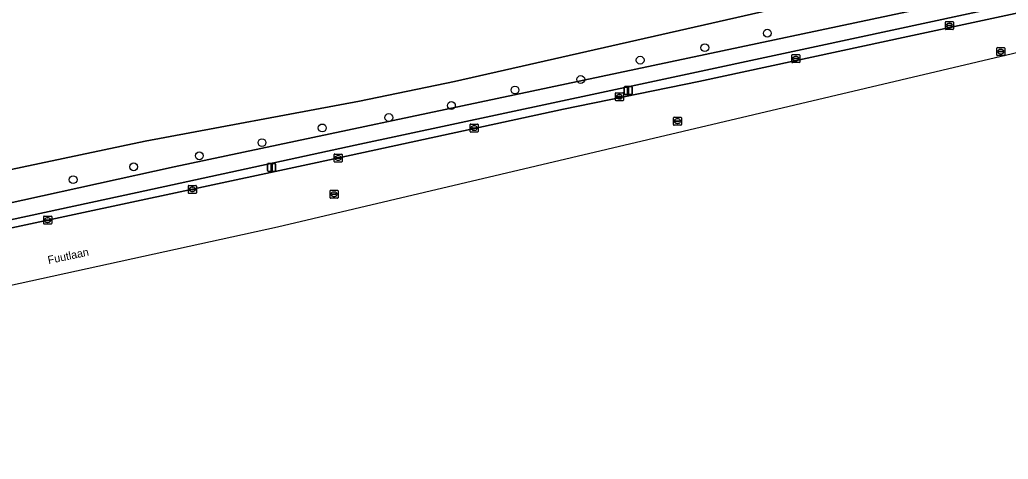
# Model space of a CAD drawing. Extents: x 161477 to 163040, y 383680 to 384871.
# Drawn here: x 162018.6 to 162142.1, y 383712.9 to 383767.8 of the extents above; entities that cross this region are included whole.
import ezdxf

# ---------------------------------------------------------------- set-up
doc = ezdxf.new("R2010")
doc.units = 0
for name, color, linetype in [('IMGEO_Boom', 7, 'Continuous'), ('IMGEO_Erf', 7, 'Continuous'), ('IMGEO_Groenvoorziening', 7, 'Continuous'), ('IMGEO_Hek', 7, 'Continuous'), ('IMGEO_Kolk', 7, 'Continuous'), ('IMGEO_Lichtmast', 7, 'Continuous'), ('IMGEO_Openbare_ruimte_label', 7, 'Continuous'), ('IMGEO_Rijbaan_lokaal_open', 7, 'Continuous'), ('IMGEO_Rioolput', 7, 'Continuous'), ('IMGEO_Voetpad_open', 7, 'Continuous')]:
    doc.layers.add(name, color=color, linetype=linetype)

msp = doc.modelspace()

# ---------------------------------------------------------------- linework, layer by layer
at = {"layer": 'IMGEO_Boom'}
for centre in [(162111.98, 383766.1), (162104.17, 383764.29), (162096.09, 383762.73), (162088.67, 383760.32), (162080.44, 383759), (162072.5, 383757.06), (162064.68, 383755.56), (162056.36, 383754.26), (162048.83, 383752.42), (162041, 383750.78), (162032.8, 383749.4), (162025.23, 383747.79)]:
    msp.add_circle(centre, 0.489, dxfattribs=at)
at = {"layer": 'IMGEO_Erf'}
msp.add_lwpolyline([(161913.96, 383727.2), (162034.23, 383752.62), (162061.02, 383757.62), (162072.88, 383760.06), (162200.21, 383788.99), (162215.71, 383792.24), (162226.94, 383794.59), (162253.58, 383800.74), (162261.09, 383802.89), (162298.92, 383814.56), (162300.16, 383814.95), (162305.42, 383816.57), (162306.83, 383817), (162311.78, 383818.53), (162312.56, 383818.77), (162312.8, 383817.2), (162313.95, 383815.04), (162315.67, 383812.77), (162316.14, 383812.14)], dxfattribs=at)
at = {"layer": 'IMGEO_Groenvoorziening'}
for points in [[(162298.92, 383814.56), (162261.09, 383802.89), (162253.58, 383800.74), (162226.94, 383794.59), (162215.71, 383792.24), (162200.21, 383788.99), (162072.88, 383760.06), (162061.02, 383757.62), (162034.23, 383752.62), (161913.96, 383727.2)], [(162007.91, 383740.73), (162033.22, 383746.19), (162060.49, 383752.12), (162097.3, 383759.98), (162118.07, 383764.45), (162141.54, 383769.48), (162180.49, 383777.87), (162190.22, 383779.97), (162198.07, 383781.8), (162206.11, 383783.95), (162214.63, 383786.44), (162216.75, 383787.01), (162217.08, 383787.12), (162231.35, 383791.72), (162216.7, 383788.57), (162197.76, 383783.49), (162191.42, 383781.95), (162037.84, 383749.41), (161933.79, 383726.48)], [(161933.79, 383726.48), (162037.84, 383749.41), (162191.42, 383781.95), (162197.76, 383783.49), (162216.7, 383788.57)]]:
    msp.add_lwpolyline(points, dxfattribs=at)
at = {"layer": 'IMGEO_Hek'}
for points in [[(162061.02, 383757.62), (162072.88, 383760.06), (162200.21, 383788.99), (162215.71, 383792.24)], [(161846.44, 383712.85), (161847.77, 383713.09), (161851.78, 383713.8), (161862.58, 383715.7), (161882.57, 383720.16), (161913.96, 383727.2), (162034.23, 383752.62), (162061.02, 383757.62)]]:
    msp.add_lwpolyline(points, dxfattribs=at)
at = {"layer": 'IMGEO_Kolk'}
for p, q in [((162134.23, 383766.63), (162134.23, 383767.49)), ((162134.3, 383767.56), (162135.15, 383767.56)), ((162134.72, 383767.34), (162134.74, 383767.34)), ((162135.23, 383767.49), (162135.23, 383766.63)), ((162135.15, 383766.56), (162134.3, 383766.56)), ((162134.49, 383767.05), (162134.49, 383767.07)), ((162134.53, 383767.1), (162134.93, 383767.1)), ((162134.92, 383767.02), (162134.53, 383767.02)), ((162134.74, 383766.78), (162134.71, 383766.78)), ((162134.97, 383767.07), (162134.97, 383767.05)), ((162115.04, 383762.49), (162115.04, 383763.35)), ((162115.11, 383763.42), (162115.96, 383763.42)), ((162115.96, 383762.42), (162115.11, 383762.42)), ((162115.3, 383762.91), (162115.3, 383762.93)), ((162115.34, 383762.96), (162115.74, 383762.96)), ((162115.73, 383762.88), (162115.34, 383762.88)), ((162115.55, 383762.64), (162115.52, 383762.64)), ((162115.53, 383763.2), (162115.55, 383763.2)), ((162115.78, 383762.93), (162115.78, 383762.91)), ((162116.04, 383763.35), (162116.04, 383762.49)), ((162093.07, 383758.66), (162093.92, 383758.66)), ((162092.99, 383757.74), (162092.99, 383758.59)), ((162093.92, 383757.66), (162093.07, 383757.66)), ((162093.25, 383758.16), (162093.25, 383758.17)), ((162093.29, 383758.21), (162093.69, 383758.21)), ((162093.69, 383758.12), (162093.29, 383758.12)), ((162093.48, 383758.44), (162093.51, 383758.44)), ((162093.5, 383757.88), (162093.48, 383757.88)), ((162093.74, 383758.17), (162093.74, 383758.16)), ((162093.99, 383758.59), (162093.99, 383757.74)), ((162074.84, 383753.81), (162074.84, 383754.67)), ((162074.91, 383754.74), (162075.76, 383754.74)), ((162075.76, 383753.74), (162074.91, 383753.74)), ((162075.09, 383754.23), (162075.09, 383754.25)), ((162075.53, 383754.2), (162075.13, 383754.2)), ((162075.14, 383754.28), (162075.54, 383754.28)), ((162075.32, 383754.52), (162075.35, 383754.52)), ((162075.35, 383753.96), (162075.32, 383753.96)), ((162075.58, 383754.25), (162075.58, 383754.23)), ((162075.84, 383754.67), (162075.84, 383753.81)), ((162057.85, 383750.08), (162057.85, 383750.93)), ((162057.92, 383751), (162058.77, 383751)), ((162058.77, 383750), (162057.92, 383750)), ((162058.11, 383750.5), (162058.11, 383750.51)), ((162058.15, 383750.55), (162058.55, 383750.55)), ((162058.54, 383750.46), (162058.15, 383750.46)), ((162058.36, 383750.22), (162058.33, 383750.22)), ((162058.34, 383750.78), (162058.36, 383750.78)), ((162058.59, 383750.51), (162058.59, 383750.5)), ((162058.85, 383750.93), (162058.85, 383750.08)), ((162039.63, 383746.15), (162039.63, 383747)), ((162039.7, 383747.08), (162040.56, 383747.08)), ((162039.89, 383746.57), (162039.89, 383746.58)), ((162039.93, 383746.62), (162040.33, 383746.62)), ((162040.32, 383746.53), (162039.93, 383746.53)), ((162040.14, 383746.3), (162040.11, 383746.3)), ((162040.12, 383746.86), (162040.14, 383746.86)), ((162040.37, 383746.58), (162040.37, 383746.57)), ((162040.63, 383747), (162040.63, 383746.15)), ((162040.56, 383746.08), (162039.7, 383746.08)), ((162021.55, 383742.31), (162021.55, 383743.17)), ((162021.62, 383743.24), (162022.47, 383743.24)), ((162021.81, 383742.73), (162021.81, 383742.75)), ((162021.85, 383742.78), (162022.25, 383742.78)), ((162022.24, 383742.7), (162021.85, 383742.7)), ((162022.04, 383743.02), (162022.06, 383743.02)), ((162022.29, 383742.75), (162022.29, 383742.73)), ((162022.55, 383743.17), (162022.55, 383742.31)), ((162022.47, 383742.24), (162021.62, 383742.24)), ((162022.06, 383742.46), (162022.03, 383742.46))]:
    msp.add_line(p, q, dxfattribs=at)
for points in [[(162134.23, 383766.63), (162134.23, 383767.49)], [(162134.3, 383767.56), (162135.15, 383767.56)], [(162135.23, 383767.49), (162135.23, 383766.63)], [(162135.15, 383766.56), (162134.3, 383766.56)], [(162115.04, 383762.49), (162115.04, 383763.35)], [(162115.11, 383763.42), (162115.96, 383763.42)], [(162115.96, 383762.42), (162115.11, 383762.42)], [(162116.04, 383763.35), (162116.04, 383762.49)], [(162093.07, 383758.66), (162093.92, 383758.66)], [(162092.99, 383757.74), (162092.99, 383758.59)], [(162093.92, 383757.66), (162093.07, 383757.66)], [(162093.99, 383758.59), (162093.99, 383757.74)], [(162074.84, 383753.81), (162074.84, 383754.67)], [(162074.91, 383754.74), (162075.76, 383754.74)], [(162075.76, 383753.74), (162074.91, 383753.74)], [(162075.84, 383754.67), (162075.84, 383753.81)], [(162057.85, 383750.08), (162057.85, 383750.93)], [(162057.92, 383751), (162058.77, 383751)], [(162058.77, 383750), (162057.92, 383750)], [(162058.85, 383750.93), (162058.85, 383750.08)], [(162039.63, 383746.15), (162039.63, 383747)], [(162039.7, 383747.08), (162040.56, 383747.08)], [(162040.63, 383747), (162040.63, 383746.15)], [(162040.56, 383746.08), (162039.7, 383746.08)], [(162021.55, 383742.31), (162021.55, 383743.17)], [(162021.62, 383743.24), (162022.47, 383743.24)], [(162022.55, 383743.17), (162022.55, 383742.31)], [(162022.47, 383742.24), (162021.62, 383742.24)]]:
    msp.add_lwpolyline(points, dxfattribs=at)
for centre, radius, start, end in [((162134.3, 383767.48), 0.0765, 91.552, 178.448), ((162134.3, 383767.48), 0.0765, 91.552, 178.448), ((162135.15, 383767.48), 0.0765, 1.552, 88.448), ((162135.15, 383767.48), 0.0765, 1.552, 88.448), ((162134.3, 383766.63), 0.0765, 181.552, 268.448), ((162134.3, 383766.63), 0.0765, 181.552, 268.448), ((162134.53, 383767.06), 0.0403, 85.8775, 175.7526), ((162134.52, 383767.05), 0.0366, 178.938, 274.7102), ((162134.93, 383767.06), 0.043, 264.8664, 352.4533), ((162134.93, 383767.06), 0.0386, 1.7309, 96.639), ((162135.15, 383766.63), 0.0765, 271.552, 358.448), ((162135.15, 383766.63), 0.0765, 271.552, 358.448), ((162115.11, 383763.34), 0.0765, 91.552, 178.448), ((162115.11, 383763.34), 0.0765, 91.552, 178.448), ((162115.11, 383762.49), 0.0765, 181.552, 268.448), ((162115.11, 383762.49), 0.0765, 181.552, 268.448), ((162115.34, 383762.92), 0.0403, 85.8775, 175.7526), ((162115.33, 383762.91), 0.0366, 178.938, 274.7102), ((162115.74, 383762.92), 0.043, 264.8664, 352.4533), ((162115.74, 383762.92), 0.0386, 1.7309, 96.639), ((162115.96, 383763.34), 0.0765, 1.552, 88.448), ((162115.96, 383763.34), 0.0765, 1.552, 88.448), ((162115.96, 383762.49), 0.0765, 271.552, 358.448), ((162115.96, 383762.49), 0.0765, 271.552, 358.448), ((162093.07, 383758.59), 0.0765, 91.552, 178.448), ((162093.07, 383758.59), 0.0765, 91.552, 178.448), ((162093.92, 383758.59), 0.0765, 1.552, 88.448), ((162093.92, 383758.59), 0.0765, 1.552, 88.448), ((162093.07, 383757.74), 0.0765, 181.552, 268.448), ((162093.07, 383757.74), 0.0765, 181.552, 268.448), ((162093.29, 383758.17), 0.0403, 85.8775, 175.7526), ((162093.29, 383758.16), 0.0366, 178.938, 274.7102), ((162093.7, 383758.17), 0.0386, 1.7309, 96.639), ((162093.69, 383758.16), 0.043, 264.8664, 352.4533), ((162093.92, 383757.74), 0.0765, 271.552, 358.448), ((162093.92, 383757.74), 0.0765, 271.552, 358.448), ((162074.91, 383754.67), 0.0765, 91.552, 178.448), ((162074.91, 383754.67), 0.0765, 91.552, 178.448), ((162074.91, 383753.82), 0.0765, 181.552, 268.448), ((162074.91, 383753.82), 0.0765, 181.552, 268.448), ((162075.14, 383754.24), 0.0403, 85.8775, 175.7526), ((162075.13, 383754.23), 0.0366, 178.938, 274.7102), ((162075.54, 383754.24), 0.043, 264.8664, 352.4533), ((162075.54, 383754.25), 0.0386, 1.7309, 96.639), ((162075.76, 383754.67), 0.0765, 1.552, 88.448), ((162075.76, 383754.67), 0.0765, 1.552, 88.448), ((162075.76, 383753.82), 0.0765, 271.552, 358.448), ((162075.76, 383753.82), 0.0765, 271.552, 358.448), ((162057.92, 383750.93), 0.0765, 91.552, 178.448), ((162057.92, 383750.93), 0.0765, 91.552, 178.448), ((162057.92, 383750.08), 0.0765, 181.552, 268.448), ((162057.92, 383750.08), 0.0765, 181.552, 268.448), ((162058.15, 383750.51), 0.0403, 85.8775, 175.7526), ((162058.14, 383750.5), 0.0366, 178.938, 274.7102), ((162058.55, 383750.5), 0.043, 264.8664, 352.4533), ((162058.55, 383750.51), 0.0386, 1.7309, 96.639), ((162058.77, 383750.93), 0.0765, 1.552, 88.448), ((162058.77, 383750.93), 0.0765, 1.552, 88.448), ((162058.77, 383750.08), 0.0765, 271.552, 358.448), ((162058.77, 383750.08), 0.0765, 271.552, 358.448), ((162039.7, 383747), 0.0765, 91.552, 178.448), ((162039.7, 383747), 0.0765, 91.552, 178.448), ((162039.93, 383746.58), 0.0403, 85.8775, 175.7526), ((162039.92, 383746.57), 0.0366, 178.938, 274.7102), ((162040.33, 383746.58), 0.043, 264.8664, 352.4533), ((162040.33, 383746.58), 0.0386, 1.7309, 96.639), ((162040.55, 383747), 0.0765, 1.552, 88.448), ((162040.55, 383747), 0.0765, 1.552, 88.448), ((162039.7, 383746.15), 0.0765, 181.552, 268.448), ((162039.7, 383746.15), 0.0765, 181.552, 268.448), ((162040.55, 383746.15), 0.0765, 271.552, 358.448), ((162040.55, 383746.15), 0.0765, 271.552, 358.448), ((162021.62, 383743.16), 0.0765, 91.552, 178.448), ((162021.62, 383743.16), 0.0765, 91.552, 178.448), ((162021.85, 383742.74), 0.0403, 85.8775, 175.7526), ((162021.84, 383742.73), 0.0366, 178.938, 274.7102), ((162022.25, 383742.74), 0.043, 264.8664, 352.4533), ((162022.25, 383742.74), 0.0386, 1.7309, 96.639), ((162022.47, 383743.16), 0.0765, 1.552, 88.448), ((162022.47, 383743.16), 0.0765, 1.552, 88.448), ((162021.62, 383742.32), 0.0765, 181.552, 268.448), ((162021.62, 383742.32), 0.0765, 181.552, 268.448), ((162022.47, 383742.32), 0.0765, 271.552, 358.448), ((162022.47, 383742.32), 0.0765, 271.552, 358.448)]:
    msp.add_arc(centre, radius, start, end, dxfattribs=at)
for centre, major_axis, ratio, start_param, end_param in [((162134.71, 383767.06), (-0.387, 0.002), 0.722429, 4.712389, 7.853982), ((162134.74, 383767.06), (-0.39, 0.002), 0.717154, 1.570796, 4.712389), ((162115.52, 383762.92), (-0.387, 0.002), 0.722429, 4.712389, 7.853982), ((162115.55, 383762.92), (-0.39, 0.002), 0.717154, 1.570796, 4.712389), ((162093.48, 383758.16), (-0.387, 0.002), 0.722429, 4.712389, 7.853982), ((162093.5, 383758.16), (-0.39, 0.002), 0.717154, 1.570796, 4.712389), ((162075.32, 383754.24), (-0.387, 0.002), 0.722429, 4.712389, 7.853982), ((162075.35, 383754.24), (-0.39, 0.002), 0.717154, 1.570796, 4.712389), ((162058.33, 383750.5), (-0.387, 0.002), 0.722429, 4.712389, 7.853982), ((162058.36, 383750.5), (-0.39, 0.002), 0.717154, 1.570796, 4.712389), ((162040.12, 383746.58), (-0.387, 0.002), 0.722429, 4.712389, 7.853982), ((162040.14, 383746.58), (-0.39, 0.002), 0.717154, 1.570796, 4.712389), ((162022.03, 383742.74), (-0.387, 0.002), 0.722429, 4.712389, 7.853982), ((162022.06, 383742.74), (-0.39, 0.002), 0.717154, 1.570796, 4.712389)]:
    msp.add_ellipse(centre, major_axis=major_axis, ratio=ratio, start_param=start_param, end_param=end_param, dxfattribs=at)
at = {"layer": 'IMGEO_Lichtmast'}
for p, q in [((162094.09, 383758.54), (162094.09, 383759.34)), ((162094.09, 383759.34), (162094.09, 383758.54)), ((162094.19, 383759.44), (162094.97, 383759.44)), ((162094.97, 383759.44), (162094.19, 383759.44)), ((162095.07, 383759.34), (162095.07, 383758.54)), ((162095.07, 383758.54), (162095.07, 383759.34)), ((162094.97, 383758.44), (162094.19, 383758.44)), ((162094.19, 383758.44), (162094.97, 383758.44)), ((162049.54, 383748.93), (162049.54, 383749.73)), ((162049.54, 383749.73), (162049.54, 383748.93)), ((162049.64, 383749.83), (162050.43, 383749.83)), ((162050.43, 383749.83), (162049.64, 383749.83)), ((162050.43, 383748.83), (162049.64, 383748.83)), ((162049.64, 383748.83), (162050.43, 383748.83)), ((162050.53, 383749.73), (162050.53, 383748.93)), ((162050.53, 383748.93), (162050.53, 383749.73))]:
    msp.add_line(p, q, dxfattribs=at)
for points in [[(162094.5, 383759.32), (162094.65, 383759.32), (162094.65, 383758.57), (162094.5, 383758.57), (162094.5, 383759.32)], [(162049.96, 383749.71), (162050.11, 383749.71), (162050.11, 383748.96), (162049.96, 383748.96), (162049.96, 383749.71)]]:
    msp.add_lwpolyline(points, dxfattribs=at)
for centre, start, end in [((162094.19, 383759.34), 90, 180), ((162094.19, 383759.34), 90, 180), ((162094.97, 383759.34), 0, 90), ((162094.97, 383759.34), 360, 90), ((162094.19, 383758.54), 180, 270), ((162094.19, 383758.54), 180, 270), ((162094.97, 383758.54), 270, 0), ((162094.97, 383758.54), 270, 0), ((162049.64, 383749.73), 90, 180), ((162049.64, 383749.73), 90, 180), ((162049.64, 383748.93), 180, 270), ((162049.64, 383748.93), 180, 270), ((162050.43, 383749.73), 0, 90), ((162050.43, 383749.73), 360, 90), ((162050.43, 383748.93), 270, 0), ((162050.43, 383748.93), 270, 0)]:
    msp.add_arc(centre, 0.1, start, end, dxfattribs=at)
at = {"layer": 'IMGEO_Rijbaan_lokaal_open'}
msp.add_lwpolyline([(161951.21, 383720.12), (162050.78, 383741.89), (162225.64, 383783.2), (162254.66, 383792.5), (162253.66, 383796.86), (162244.29, 383794.61), (162240.84, 383793.55), (162224.8, 383788.56), (162219.62, 383786.85), (162219.33, 383786.78), (162214.48, 383785.25), (162201.98, 383781.65), (162200.19, 383781.17), (162199.34, 383780.94), (162193.85, 383779.62), (162173.23, 383775.14), (162160.65, 383772.41), (162129.52, 383765.69), (162103.41, 383760.08), (162086.49, 383756.59), (162061.51, 383751.2), (162055.16, 383749.81), (162038.61, 383746.29), (162000, 383738.01)], dxfattribs=at)
at = {"layer": 'IMGEO_Rioolput'}
for p, q in [((162140.66, 383763.37), (162140.66, 383764.22)), ((162140.73, 383764.3), (162141.58, 383764.3)), ((162140.91, 383763.79), (162140.91, 383763.8)), ((162141.35, 383763.75), (162140.95, 383763.75)), ((162140.96, 383763.84), (162141.35, 383763.84)), ((162141.14, 383764.08), (162141.17, 383764.08)), ((162141.4, 383763.8), (162141.4, 383763.79)), ((162141.66, 383764.22), (162141.66, 383763.37)), ((162141.58, 383763.3), (162140.73, 383763.3)), ((162141.17, 383763.52), (162141.14, 383763.52)), ((162100.25, 383754.68), (162100.25, 383755.54)), ((162100.32, 383755.61), (162101.17, 383755.61)), ((162100.51, 383755.1), (162100.51, 383755.12)), ((162100.55, 383755.15), (162100.95, 383755.15)), ((162100.94, 383755.07), (162100.55, 383755.07)), ((162100.74, 383755.39), (162100.76, 383755.39)), ((162100.99, 383755.12), (162100.99, 383755.1)), ((162101.25, 383755.54), (162101.25, 383754.68)), ((162101.17, 383754.61), (162100.32, 383754.61)), ((162100.76, 383754.83), (162100.73, 383754.83)), ((162057.33, 383745.54), (162057.33, 383746.4)), ((162057.41, 383746.47), (162058.26, 383746.47)), ((162057.82, 383746.25), (162057.85, 383746.25)), ((162058.34, 383746.4), (162058.34, 383745.54)), ((162058.26, 383745.47), (162057.41, 383745.47)), ((162057.59, 383745.96), (162057.59, 383745.98)), ((162058.03, 383745.93), (162057.63, 383745.93)), ((162057.64, 383746.01), (162058.03, 383746.01)), ((162057.84, 383745.69), (162057.82, 383745.69)), ((162058.08, 383745.98), (162058.08, 383745.96))]:
    msp.add_line(p, q, dxfattribs=at)
for points in [[(162140.66, 383763.37), (162140.66, 383764.22)], [(162140.73, 383764.3), (162141.58, 383764.3)], [(162141.66, 383764.22), (162141.66, 383763.37)], [(162141.58, 383763.3), (162140.73, 383763.3)], [(162100.25, 383754.68), (162100.25, 383755.54)], [(162100.32, 383755.61), (162101.17, 383755.61)], [(162101.25, 383755.54), (162101.25, 383754.68)], [(162101.17, 383754.61), (162100.32, 383754.61)], [(162057.33, 383745.54), (162057.33, 383746.4)], [(162057.41, 383746.47), (162058.26, 383746.47)], [(162058.34, 383746.4), (162058.34, 383745.54)], [(162058.26, 383745.47), (162057.41, 383745.47)]]:
    msp.add_lwpolyline(points, dxfattribs=at)
for centre, radius, start, end in [((162140.73, 383764.22), 0.0765, 91.552, 178.448), ((162140.73, 383764.22), 0.0765, 91.552, 178.448), ((162140.95, 383763.8), 0.0403, 85.8775, 175.7526), ((162140.95, 383763.79), 0.0366, 178.938, 274.7102), ((162141.36, 383763.8), 0.0386, 1.7309, 96.639), ((162141.36, 383763.8), 0.043, 264.8664, 352.4533), ((162141.58, 383764.22), 0.0765, 1.552, 88.448), ((162141.58, 383764.22), 0.0765, 1.552, 88.448), ((162140.73, 383763.37), 0.0765, 181.552, 268.448), ((162140.73, 383763.37), 0.0765, 181.552, 268.448), ((162141.58, 383763.37), 0.0765, 271.552, 358.448), ((162141.58, 383763.37), 0.0765, 271.552, 358.448), ((162100.32, 383755.53), 0.0765, 91.552, 178.448), ((162100.32, 383755.53), 0.0765, 91.552, 178.448), ((162100.55, 383755.11), 0.0403, 85.8775, 175.7526), ((162100.54, 383755.1), 0.0366, 178.938, 274.7102), ((162100.95, 383755.11), 0.043, 264.8664, 352.4533), ((162100.95, 383755.11), 0.0386, 1.7309, 96.639), ((162101.17, 383755.53), 0.0765, 1.552, 88.448), ((162101.17, 383755.53), 0.0765, 1.552, 88.448), ((162100.32, 383754.68), 0.0765, 181.552, 268.448), ((162100.32, 383754.68), 0.0765, 181.552, 268.448), ((162101.17, 383754.68), 0.0765, 271.552, 358.448), ((162101.17, 383754.68), 0.0765, 271.552, 358.448), ((162057.41, 383746.39), 0.0765, 91.552, 178.448), ((162057.41, 383746.39), 0.0765, 91.552, 178.448), ((162058.26, 383746.39), 0.0765, 1.552, 88.448), ((162058.26, 383746.39), 0.0765, 1.552, 88.448), ((162057.41, 383745.55), 0.0765, 181.552, 268.448), ((162057.41, 383745.55), 0.0765, 181.552, 268.448), ((162057.63, 383745.97), 0.0403, 85.8775, 175.7526), ((162057.63, 383745.96), 0.0366, 178.938, 274.7102), ((162058.04, 383745.97), 0.0386, 1.7309, 96.639), ((162058.03, 383745.97), 0.043, 264.8664, 352.4533), ((162058.26, 383745.55), 0.0765, 271.552, 358.448), ((162058.26, 383745.55), 0.0765, 271.552, 358.448)]:
    msp.add_arc(centre, radius, start, end, dxfattribs=at)
for centre, major_axis, ratio, start_param, end_param in [((162141.14, 383763.8), (-0.387, 0.002), 0.722429, 4.712389, 7.853982), ((162141.17, 383763.8), (-0.39, 0.002), 0.717154, 1.570796, 4.712389), ((162100.73, 383755.11), (-0.387, 0.002), 0.722429, 4.712389, 7.853982), ((162100.76, 383755.11), (-0.39, 0.002), 0.717154, 1.570796, 4.712389), ((162057.82, 383745.97), (-0.387, 0.002), 0.722429, 4.712389, 7.853982), ((162057.85, 383745.97), (-0.39, 0.002), 0.717154, 1.570796, 4.712389)]:
    msp.add_ellipse(centre, major_axis=major_axis, ratio=ratio, start_param=start_param, end_param=end_param, dxfattribs=at)
at = {"layer": 'IMGEO_Voetpad_open'}
for points in [[(162296.32, 383807.07), (162272.19, 383801.91), (162257.67, 383799.06), (162245.14, 383796.02), (162238.76, 383794.1), (162231.35, 383791.72), (162217.08, 383787.12), (162216.75, 383787.01), (162214.63, 383786.44), (162206.11, 383783.95), (162198.07, 383781.8), (162190.22, 383779.97), (162180.49, 383777.87), (162141.54, 383769.48), (162118.07, 383764.45), (162097.3, 383759.98), (162060.49, 383752.12), (162033.22, 383746.19), (162007.91, 383740.73)], [(162000, 383738.01), (162038.61, 383746.29), (162055.16, 383749.81), (162061.51, 383751.2), (162086.49, 383756.59), (162103.41, 383760.08), (162129.52, 383765.69), (162160.65, 383772.41), (162173.23, 383775.14), (162193.85, 383779.62), (162199.34, 383780.94), (162200.19, 383781.17), (162201.98, 383781.65), (162214.48, 383785.25), (162219.33, 383786.78), (162219.62, 383786.85), (162224.8, 383788.56), (162240.84, 383793.55)]]:
    msp.add_lwpolyline(points, dxfattribs=at)

# ---------------------------------------------------------------- texts
at = {"layer": 'IMGEO_Openbare_ruimte_label'}
msp.add_text('Fuutlaan', height=1, rotation=11.9506, dxfattribs=at).set_placement((162022.17, 383737.24))

doc.saveas('drawing.dxf')
